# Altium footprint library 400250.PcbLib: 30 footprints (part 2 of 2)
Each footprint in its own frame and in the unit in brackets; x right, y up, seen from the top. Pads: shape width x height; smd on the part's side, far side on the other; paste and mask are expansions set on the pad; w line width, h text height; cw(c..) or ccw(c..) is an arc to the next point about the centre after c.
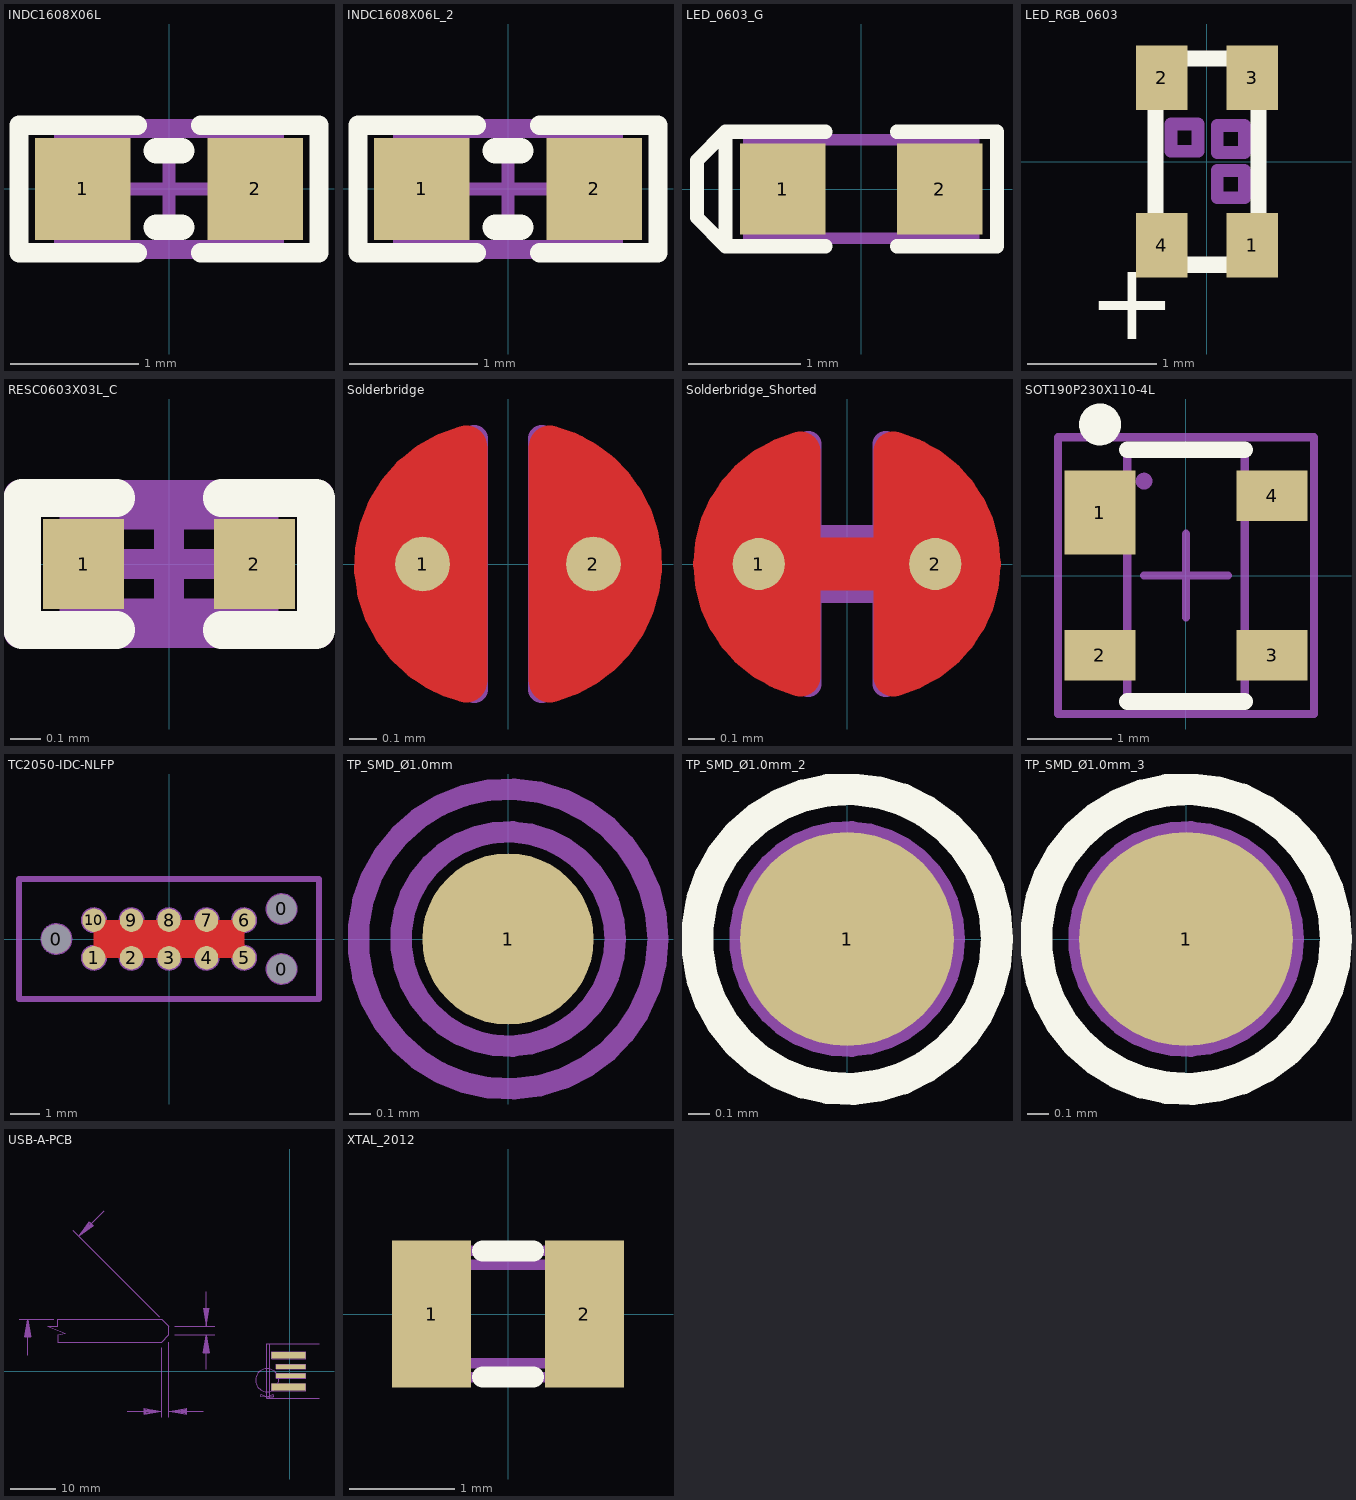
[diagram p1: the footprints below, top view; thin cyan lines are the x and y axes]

## INDC1608X06L [mm] "Chip Inductor, 2-Leads, Body 1.6x0.8mm, IPC High Density"
height 0.55
pads (2):
  rect 0.75x0.8 smd: 1(-0.675,0) 2(0.675,0)
Top Overlay:
  lines w0.152: -0.25,-0.5 -1.175,-0.5 -1.175,0.5 -0.25,0.5 ; 0.25,-0.5 1.175,-0.5 1.175,0.5 0.25,0.5
  lines w0.2: -0.1,-0.3 0.1,-0.3 ; -0.1,0.3 0.1,0.3
Mechanical 7:
  lines w0.1: -0.85,-0.45 0.85,-0.45 0.85,0.45 -0.85,0.45 -0.85,-0.45
  text ".Designator" at -0.214,-0.152 h0.3
Mechanical 15:
  lines w0.1: -0.45,0 0.45,0 ; 0,-0.45 0,0.45 ; -1.175,-0.5 -1.175,0.5 1.175,0.5 1.175,-0.5 -1.175,-0.5
3D body "User Library-Chip Inductor.step": height 0.8, standoff 0, extent -0.8,-0.475 0.8,0.475

## INDC1608X06L_2 [mm]
pads (2):
  rect 0.75x0.8 smd: 1(-0.675,0) 2(0.675,0)
Top Overlay:
  lines w0.152: -0.25,-0.5 -1.175,-0.5 -1.175,0.5 -0.25,0.5 ; 0.25,-0.5 1.175,-0.5 1.175,0.5 0.25,0.5
  lines w0.2: -0.1,-0.3 0.1,-0.3 ; -0.1,0.3 0.1,0.3
Mechanical 7:
  lines w0.1: -0.85,-0.45 0.85,-0.45 0.85,0.45 -0.85,0.45 -0.85,-0.45
  text ".Designator" at 0.255,0.178 h0.3
Mechanical 15:
  lines w0.1: -0.45,0 0.45,0 ; 0,-0.45 0,0.45 ; -1.175,-0.5 -1.175,0.5 1.175,0.5 1.175,-0.5 -1.175,-0.5
3D body "User Library-Chip Inductor.step": height 0.8, standoff 0, extent -0.8,-0.475 0.8,0.475

## LED_0603_G [mil] "SMD Super Bright LED, GREEN"
height 23.62
pads (2):
  rect 30x32 smd: 1(-27.5,0) 2(27.5,0)
Top Overlay:
  lines w5: -12.5,-20 -47.5,-20 ; -12.5,20 -47.5,20 ; 12.5,-20 47.5,-20 47.5,20 12.5,20 ; -47.5,-20 -57.5,-10 -57.5,10 -47.5,20 ; -47.5,-20 -47.5,20
Mechanical 7:
  lines w3.94: -27.56,-17.26 -27.56,17.26 ; -23.62,-17.26 -23.62,17.26 ; 23.62,-17.26 23.62,17.26 ; 27.56,-17.26 27.56,17.26 ; -39.37,-17.26 -39.37,17.26 39.37,17.26 39.37,-17.26 -39.37,-17.26
  text ".Designator" at -16,-5 h12
3D body "User Library-led_0603_green.step": height 23.62, standoff 0, extent -31.63,-15.75 32.15,15.75

## LED_RGB_0603 [mm]
height 0.5
pads (4):
  rect 0.4x0.5 smd paste+0: 1(0.35,-0.65) 2(-0.35,0.65) 3(0.35,0.65) 4(-0.35,-0.65)
Top Overlay:
  lines w0.125: -0.4,-0.8 0.4,-0.8 0.4,0.8 -0.4,0.8 -0.4,-0.8
  text "+" at -0.925,-1.375 h0.6
Mechanical 7:
  lines w0.1: -0.4,-0.65 cw(c-0.4,-0.8) -0.25,-0.8 0.25,-0.8 cw(c0.4,-0.8) 0.4,-0.65 0.4,0.65 cw(c0.4,0.8) 0.25,0.8 -0.25,0.8 cw(c-0.4,0.8) -0.4,0.65 -0.4,-0.65 ; -0.28,0.08 -0.28,0.29 -0.07,0.29 -0.07,0.08 -0.28,0.08 ; 0.08,-0.28 0.29,-0.28 0.29,-0.07 0.08,-0.07 0.08,-0.28 ; 0.08,0.07 0.29,0.07 0.29,0.28 0.08,0.28 0.08,0.07
  text ".Designator" at 0.533,0.406 h0.3
3D body: height 0.18, standoff 0, extent -0.4,-0.8 0.4,0.8
3D body: height 0.5, standoff 0.18, extent -0.4,-0.8 0.4,0.8
3D body: height 0.27, standoff 0.18, extent -0.325,0.025 -0.025,0.325
3D body: height 0.27, standoff 0.18, extent 0.025,0.025 0.325,0.325
3D body: height 0.27, standoff 0.18, extent 0.025,-0.325 0.325,-0.025

## RESC0603X03L_C [mm] "Chip Resistor, 2-Leads, Body 0.6x0.3mm, IPC High Density"
height 0.33
pads (2):
  rect 0.27x0.3 smd: 1(-0.285,0) 2(0.285,0)
Top Overlay:
  lines w0.125: -0.175,-0.22 -0.49,-0.22 -0.49,0.22 -0.175,0.22 ; 0.175,-0.22 0.49,-0.22 0.49,0.22 0.175,0.22
Mechanical 7:
  lines w0.1: -0.315,-0.165 -0.315,0.165 0.315,0.165 0.315,-0.165 -0.315,-0.165
  text ".Designator" at 0.432,-0.152 h0.3
Mechanical 15:
  lines w0.1: -0.165,0 0.165,0 ; 0,-0.165 0,0.165 ; -0.5,-0.23 -0.5,0.23 0.5,0.23 0.5,-0.23 -0.5,-0.23
3D body "User Library-res0201-1.step": height 0.23, standoff 0, extent -0.3,-0.15 0.3,0.15

## Solderbridge [mm]
height 50
pads (2):
  round 0.2 smd paste-10: 1(-0.312,0) 2(0.312,0)
Top Layer:
  region: 0.077,0.432 0.152,0.505 0.271,0.467 0.335,0.424 0.409,0.351 0.462,0.292 0.521,0.193 0.549,0.099 0.544,-0.122 0.518,-0.193 0.434,-0.33 0.351,-0.411 0.259,-0.469 0.157,-0.5 0.107,-0.483 0.077,-0.43
  region: -0.077,-0.432 -0.152,-0.505 -0.271,-0.467 -0.335,-0.424 -0.409,-0.351 -0.462,-0.292 -0.521,-0.193 -0.549,-0.099 -0.544,0.122 -0.518,0.193 -0.434,0.33 -0.351,0.411 -0.259,0.469 -0.157,0.5 -0.107,0.483 -0.077,0.43
  lines w0.152: -0.153,-0.431 cw(c-0.042,0) -0.312,-0.353 cw(c-0.042,0) -0.153,0.431 ; 0.153,-0.431 ccw(c0.042,0) 0.478,-0.088 ccw(c0.042,0) 0.383,0.286 ccw(c0.042,0) 0.153,0.431
Top Solder:
  circle w0.61: c-0.003,0 r0.279
Mechanical 7:
  lines w0.1: -0.123,-0.459 cw(c-0.042,0) -0.123,0.459 -0.123,-0.459 ; 0.123,-0.459 ccw(c0.042,0) 0.123,0.459 0.123,-0.459
  text ".Designator" at -0.686,0.203 h0.38

## Solderbridge_Shorted [mm]
height 9
pads (2):
  round 0.2 smd paste-10: 1(-0.338,0) 2(0.338,0)
Top Layer:
  region: 0.102,0.432 0.178,0.505 0.296,0.467 0.361,0.424 0.434,0.351 0.488,0.292 0.546,0.193 0.574,0.099 0.569,-0.122 0.544,-0.193 0.46,-0.33 0.376,-0.411 0.284,-0.469 0.183,-0.5 0.132,-0.483 0.102,-0.43
  region: -0.102,-0.432 -0.178,-0.505 -0.296,-0.467 -0.361,-0.424 -0.434,-0.351 -0.488,-0.292 -0.546,-0.193 -0.574,-0.099 -0.569,0.122 -0.544,0.193 -0.46,0.33 -0.376,0.411 -0.284,0.469 -0.183,0.5 -0.132,0.483 -0.102,0.43
  lines w0.152: -0.178,-0.431 cw(c-0.068,0) -0.178,0.431 ; 0.178,-0.431 ccw(c0.068,0) 0.178,0.431
  lines w0.203: -0.338,0 0.338,0
Top Solder:
  circle w0.61: c-0.028,0 r0.279
  circle w0.61: c0.028,0 r0.279
Mechanical 7:
  lines w0.1: -0.148,-0.459 cw(c-0.067,0) -0.148,0.459 -0.148,0.1 0.148,0.1 0.148,0.459 cw(c0.067,0) 0.148,-0.459 0.148,-0.1 -0.148,-0.1 -0.148,-0.459
  text ".Designator" at -0.635,0.635 h0.38

## SOT190P230X110-4L [mm] "SOT143, 4-Leads, Body 3.0x2.5mm (max), Pitch 1.90mm, IPC High Density"
height 1.1
pads (4):
  rect 0.85x1 smd: 1(-1.025,0.75)
  rect 0.85x0.6 smd: 2(-1.025,-0.95) 3(1.025,-0.95) 4(1.025,0.95)
Top Overlay:
  circle w0.25: c-1.025,1.8 r0.125
  lines w0.2: -0.7,-1.5 0.7,-1.5 ; -0.7,1.5 0.7,1.5
Mechanical 7:
  circle w0.1: c-0.5,1.125 r0.05
  lines w0.1: -0.7,-1.5 0.7,-1.5 0.7,1.5 -0.7,1.5 -0.7,-1.5
  text ".Designator" at -0.152,0.178 h0.3
Mechanical 15:
  lines w0.1: -0.5,0 0.5,0 ; 0,-0.5 0,0.5 ; -1.525,-1.65 1.525,-1.65 1.525,1.65 -1.525,1.65 -1.525,-1.65
3D body "User Library-sot143.step": height 1, standoff 0, extent -1.21,-1.46 1.21,1.46

## TC2050-IDC-NLFP [mil]
pads (13):
  round 39 hole 39 unplated: 0(-150,0) 0(150,-40) 0(150,40)
  round 31 smd paste-196.85: 1(-100,-25) 2(-50,-25) 3(0,-25) 4(50,-25) 5(100,-25) 6(100,25) 7(50,25) 8(0,25) 9(-50,25) 10(-100,25)
Top Layer:
  pour cut-out: -100,25 -100,-25 100,-25 100,25
Mechanical 7:
  circle w3.94: c-100,24.99 r15.45
  circle w3.94: c-100,-24.99 r15.45
  circle w3.94: c-50,-24.99 r15.45
  circle w3.94: c0,-24.99 r15.45
  circle w3.94: c0,24.99 r15.45
  circle w3.94: c-50,24.99 r15.45
  circle w3.94: c50,24.99 r15.45
  circle w3.94: c50,-24.99 r15.45
  circle w3.94: c100,-24.99 r15.45
  circle w3.94: c100,24.99 r15.45
  circle w3.94: c150,-39.98 r19.26
  circle w3.94: c150,39.98 r19.26
  circle w3.94: c-150,0 r19.26
Mechanical 8:
  circle w3.94: c-150,0 r19.26
  circle w3.94: c150,39.98 r19.26
  circle w3.94: c150,-39.98 r19.26
Mechanical 15:
  lines w7.87: -199.8,-79.92 -199.8,79.92 199.8,79.92 199.8,-79.92 -199.8,-79.92

## TP_SMD_Ø1.0mm [mm]
height 9
pads (1):
  round 0.8 smd paste-5: 1(0,0)
Mechanical 7:
  circle w0.1: c0,0 r0.7
  circle w0.1: c0,0 r0.5
  text ".Designator" at -0.85,-0.225 h0.3

## TP_SMD_Ø1.0mm_2 [mm]
pads (1):
  round 1 smd paste-5: 1(0,0)
Top Overlay:
  circle w0.15: c0,0 r0.7
Mechanical 7:
  circle w0.1: c0,0 r0.5
  circle w0.1: c0,0 r0.7
  text ".Designator" at 0.152,0.864 h0.3

## TP_SMD_Ø1.0mm_3 [mm]
pads (1):
  round 1 smd paste-5: 1(0,0)
Top Overlay:
  circle w0.15: c0,0 r0.7
Mechanical 7:
  circle w0.1: c0,0 r0.5
  circle w0.1: c0,0 r0.7
  text ".Designator" at 0.152,0.864 h0.3

## USB-A-PCB [mil]
pads (4):
  rect 296x60 smd paste-196.85: 1(-7.87,-137.8) 4(-7.87,138)
  rect 256x40 smd paste-196.85: 2(12,-39.37) 3(12,40)
Mechanical 4:
  circle w10: c-194.86,-78.49 r100
  lines w8: -2348.25,452.1 -2048.25,452.1 ; -2273.25,139.6 -2273.25,447.1 ; -1883.01,1224.42 -1193.15,534.56 -1130.65,472.06 ; -1609.35,1392.55 -1826.78,1175.12 ; -1406.48,-348.61 -1111.48,-348.61 ; -1110.75,452.1 -1048.25,389.6 -1048.25,314.6 -1110.48,252.37 ; -1110.69,-400 -1110.69,202.1 ; -1110.69,252.1 -2010.75,252.1 -2010.75,314.6 -1948.25,327.1 -2098.25,389.6 -2010.75,389.6 -2010.75,452.1 -1110.69,452.1 ; -1048.25,-400 -1048.25,252.1 ; -998.25,314.6 -648.25,314.6 ; -998.25,389.6 -648.25,389.6 ; -748.25,-347.9 -1043.25,-347.9 ; -723.25,14.6 -723.25,309.6 ; -723.25,689.6 -723.25,394.6 ; -2273.25,447.1 -2298.25,297.1 -2248.25,297.1 -2273.25,447.1 ; -1826.78,1175.12 -1703.04,1263.5 -1738.39,1298.86 -1826.78,1175.12 ; -1111.48,-348.61 -1261.48,-373.61 -1261.48,-323.61 -1111.48,-348.61 ; -1043.25,-347.9 -893.25,-322.9 -893.25,-372.9 -1043.25,-347.9 ; -723.25,309.6 -748.25,159.6 -698.25,159.6 -723.25,309.6 ; -723.25,394.6 -748.25,544.6 -698.25,544.6 -723.25,394.6 ; -2293.25,302.1 -2273.25,437.1 -2253.25,302.1 -2293.25,302.1 ; -2288.25,307.1 -2273.25,427.1 -2258.25,307.1 -2288.25,307.1 ; -2283.25,312.1 -2273.25,417.1 -2263.25,312.1 -2283.25,312.1 ; -2278.25,317.1 -2273.25,407.1 -2268.25,317.1 -2278.25,317.1 ; -1819.71,1182.18 -1710.12,1263.5 -1738.4,1291.79 -1819.71,1182.18 ; -1812.64,1189.26 -1717.19,1263.5 -1738.4,1284.71 -1812.64,1189.26 ; -1805.57,1196.33 -1724.25,1263.51 -1738.4,1277.65 -1805.57,1196.33 ; -1798.5,1203.4 -1731.32,1263.51 -1738.39,1270.58 -1798.5,1203.4 ; -1256.48,-368.61 -1121.48,-348.61 -1256.48,-328.61 -1256.48,-368.61 ; -1251.48,-363.61 -1131.48,-348.61 -1251.48,-333.61 -1251.48,-363.61 ; -1246.48,-358.61 -1141.48,-348.61 -1246.48,-338.61 -1246.48,-358.61 ; -1241.48,-353.61 -1151.48,-348.61 -1241.48,-343.61 -1241.48,-353.61 ; -1033.25,-347.9 -898.25,-327.9 -898.25,-367.9 -1033.25,-347.9 ; -1023.25,-347.9 -903.25,-332.9 -903.25,-362.9 -1023.25,-347.9 ; -1013.25,-347.9 -908.25,-337.9 -908.25,-357.9 -1013.25,-347.9 ; -1003.25,-347.9 -913.25,-342.9 -913.25,-352.9 -1003.25,-347.9 ; -743.25,164.6 -723.25,299.6 -703.25,164.6 -743.25,164.6 ; -743.25,539.6 -723.25,404.6 -703.25,539.6 -743.25,539.6 ; -738.25,169.6 -723.25,289.6 -708.25,169.6 -738.25,169.6 ; -738.25,534.6 -723.25,414.6 -708.25,534.6 -738.25,534.6 ; -733.25,174.6 -723.25,279.6 -713.25,174.6 -733.25,174.6 ; -733.25,529.6 -713.25,529.6 -723.25,424.6 -733.25,529.6 ; -728.25,179.6 -723.25,269.6 -718.25,179.6 -728.25,179.6 ; -728.25,524.6 -718.25,524.6 -723.25,434.6 -728.25,524.6
  lines w10: -250.54,-219.16 -196.7,-220.29 -247.33,-198.8 -250.54,-219.16 ; -196.86,-220.49 -146.86,-200.49 -141.86,-220.49 -196.86,-220.49
  text "0.030in [0.75mm]" at -673.25,752.1 h90
  text "45" at -1998.15,698.85 h90
  text "o" at -2098.15,861.35 h48
  text "DETAIL A" at -2548.25,2.1 h150
  text "0.025in [0.625mm]" at -1427.23,-975.58 h90
  text "SEE DETAIL A" at -150.54,-967.16 h75
Mechanical 7:
  lines w3.94: -156,-167.8 -156,-107.8 140,-107.8 140,-167.8 -156,-167.8 ; -156,108 140,108 140,168 -156,168 -156,108 ; -116,-60 -116,-19 140,-19 140,-60 -116,-60 ; -116,19.37 140,19.37 140,60.37 -116,60.37 -116,19.37
Mechanical 15:
  lines w5: -172.24,-236.22 -172.24,237 ; 255.91,-236.22 -196.85,-236.22 -196.85,237 255.91,237
  text "Card edge" at -222.44,-119.69 h62

## XTAL_2012 [mm] "XTAL SMD 2.0 x 1.2 mm"
height 0.8
pads (2):
  rect 0.75x1.4 smd: 1(-0.725,0) 2(0.725,0)
Top Overlay:
  lines w0.2: -0.24,-0.6 0.24,-0.6 ; -0.24,0.6 0.24,0.6
Mechanical 7:
  lines w0.1: -1,-0.5 cw(c-1,-0.6) -0.9,-0.6 0.9,-0.6 cw(c1,-0.6) 1,-0.5 1,0.5 cw(c1,0.6) 0.9,0.6 -0.9,0.6 cw(c-1,0.6) -1,0.5 -1,-0.5 ; -0.87,-0.37 ccw(c-0.77,-0.37) -0.77,-0.47 0.77,-0.47 ccw(c0.77,-0.37) 0.87,-0.37 0.87,0.37 ccw(c0.77,0.37) 0.77,0.47 -0.77,0.47 ccw(c-0.77,0.37) -0.87,0.37 -0.87,-0.37
  text ".Designator" at -0.254,-0.152 h0.3
3D body "User Library-ABS06.STEP": height 0.6, standoff 0, extent -1,-0.61 1,0.61
3D body: height 0.6, standoff 0.15, extent -0.825,-0.4 0.825,0.4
